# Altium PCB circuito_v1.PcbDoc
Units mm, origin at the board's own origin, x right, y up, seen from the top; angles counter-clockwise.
Board outline 81.15 x 71.75 mm, 2 copper layers (Top Layer, Bottom Layer); 45 components, 30 nets, 109 pads, 27 vias.
Unrouted connection lines stored in the file: 31.
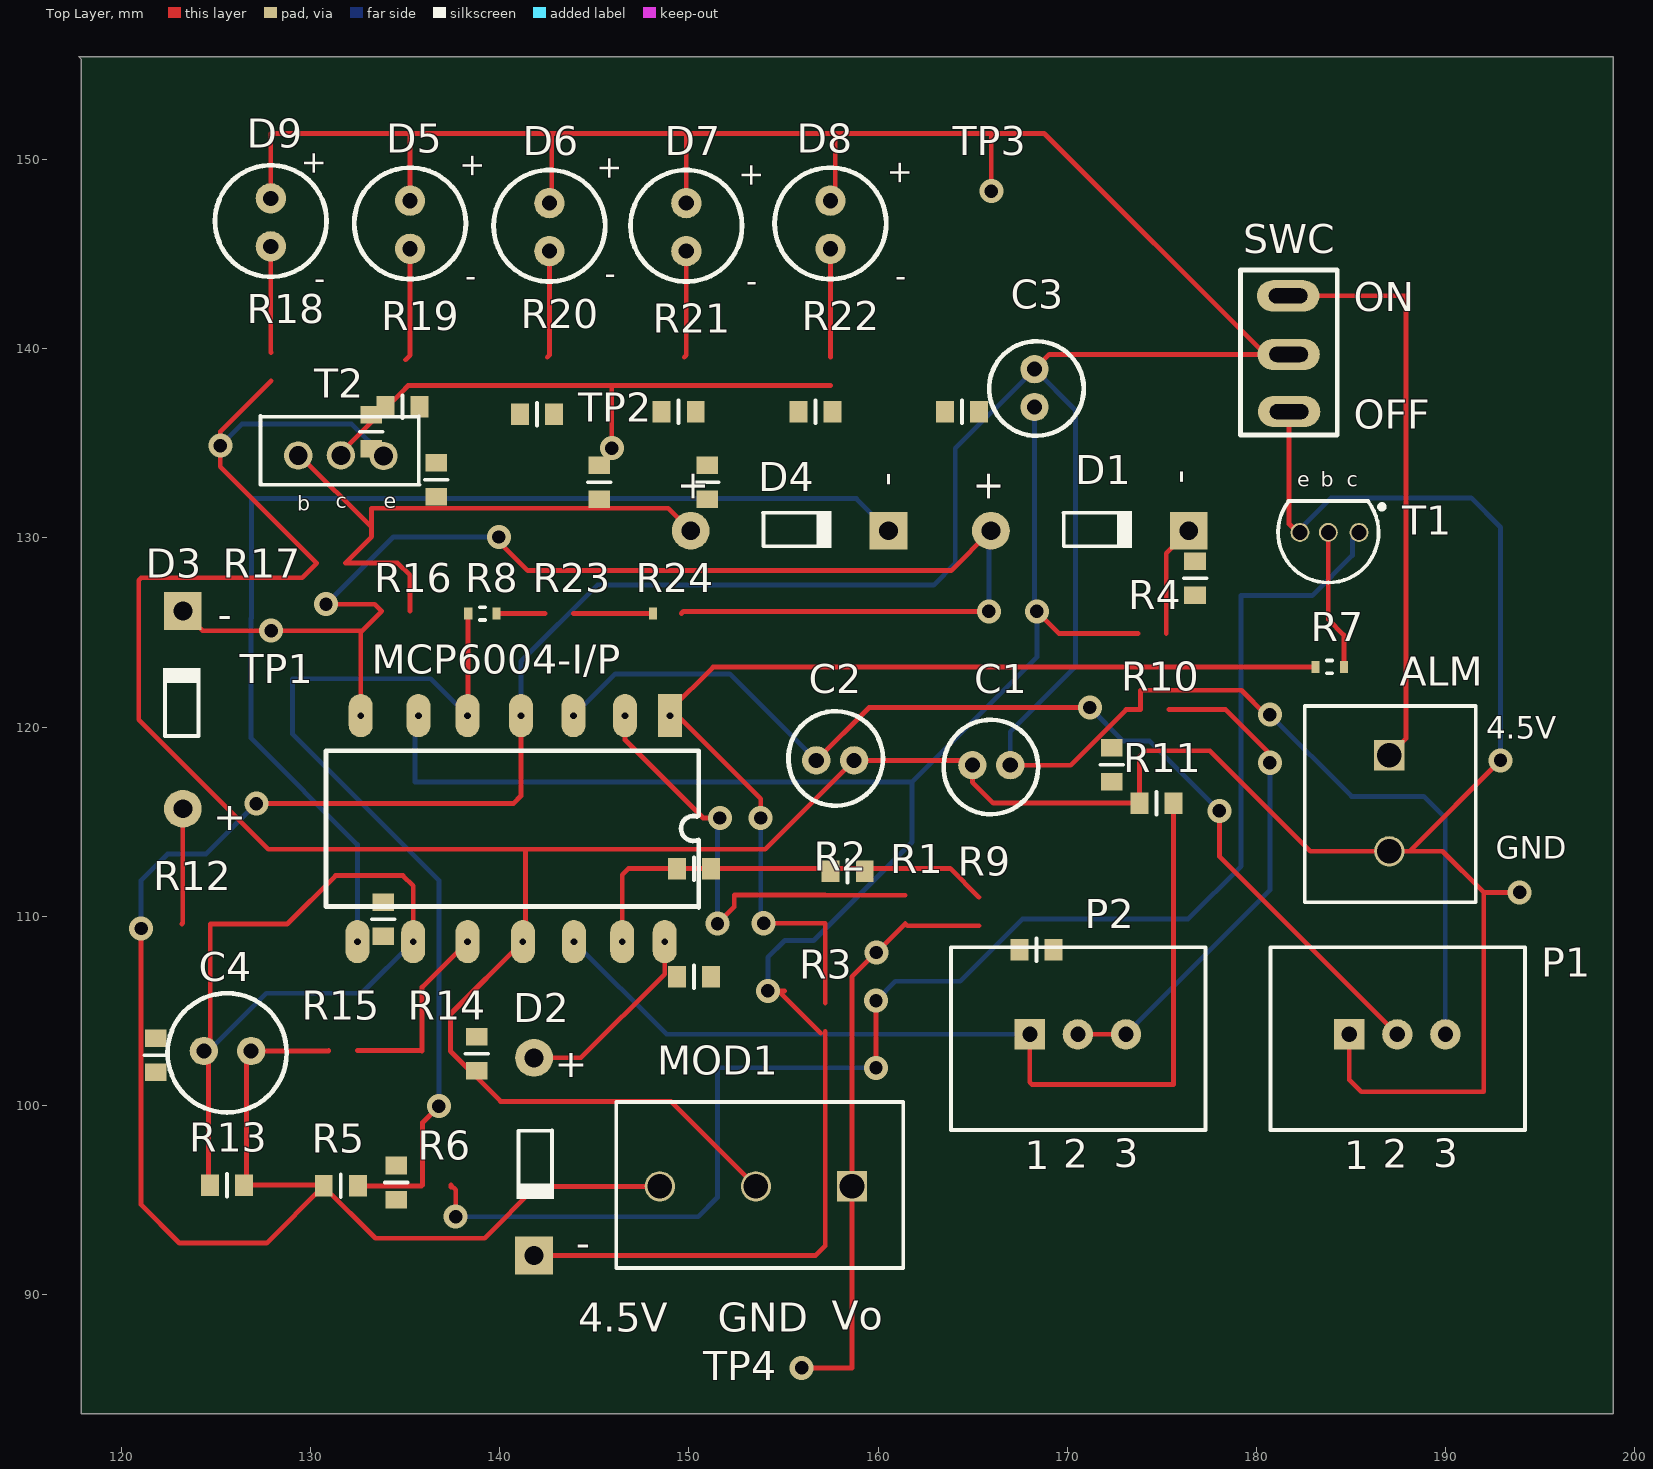
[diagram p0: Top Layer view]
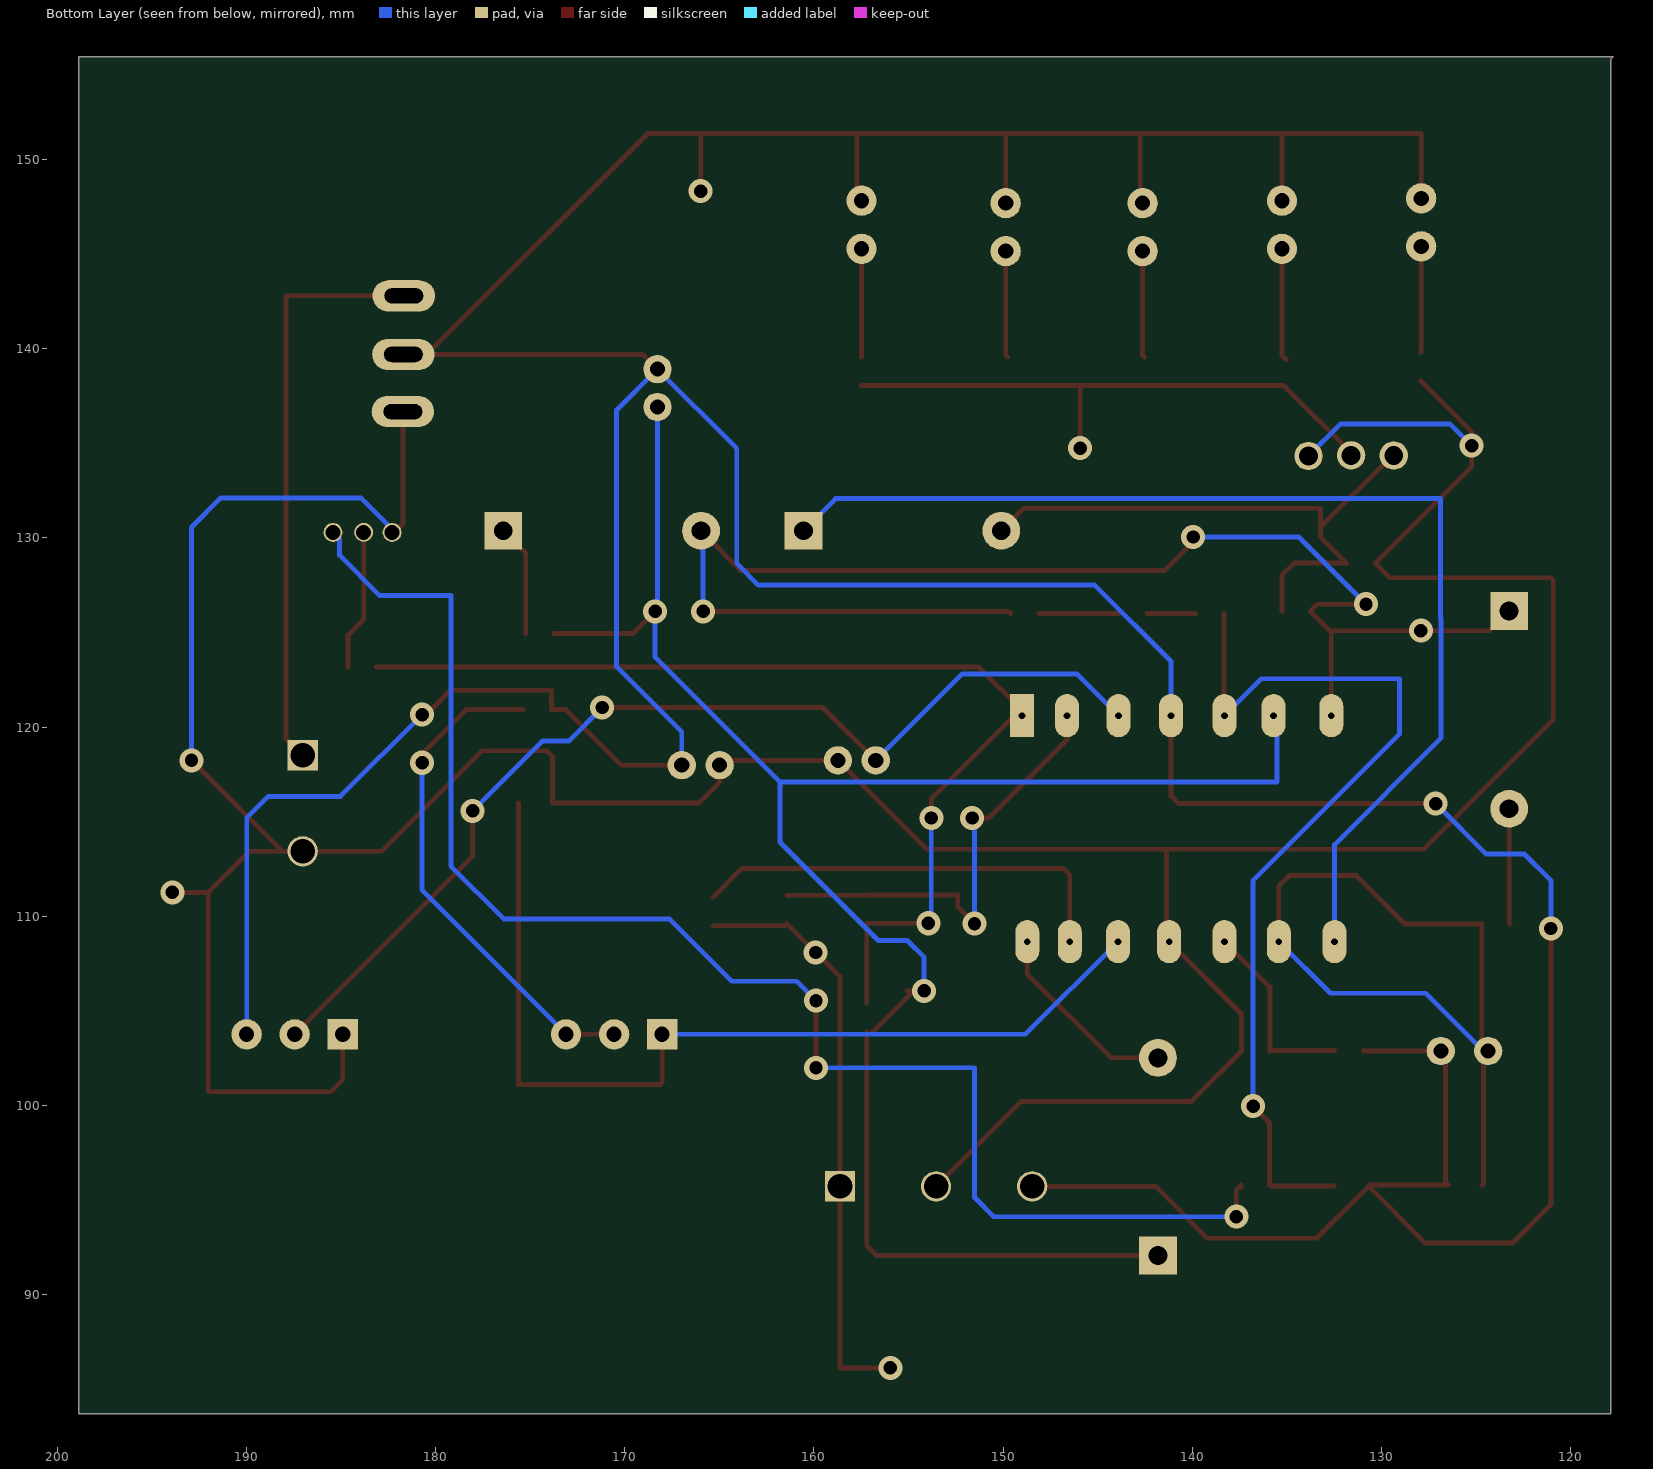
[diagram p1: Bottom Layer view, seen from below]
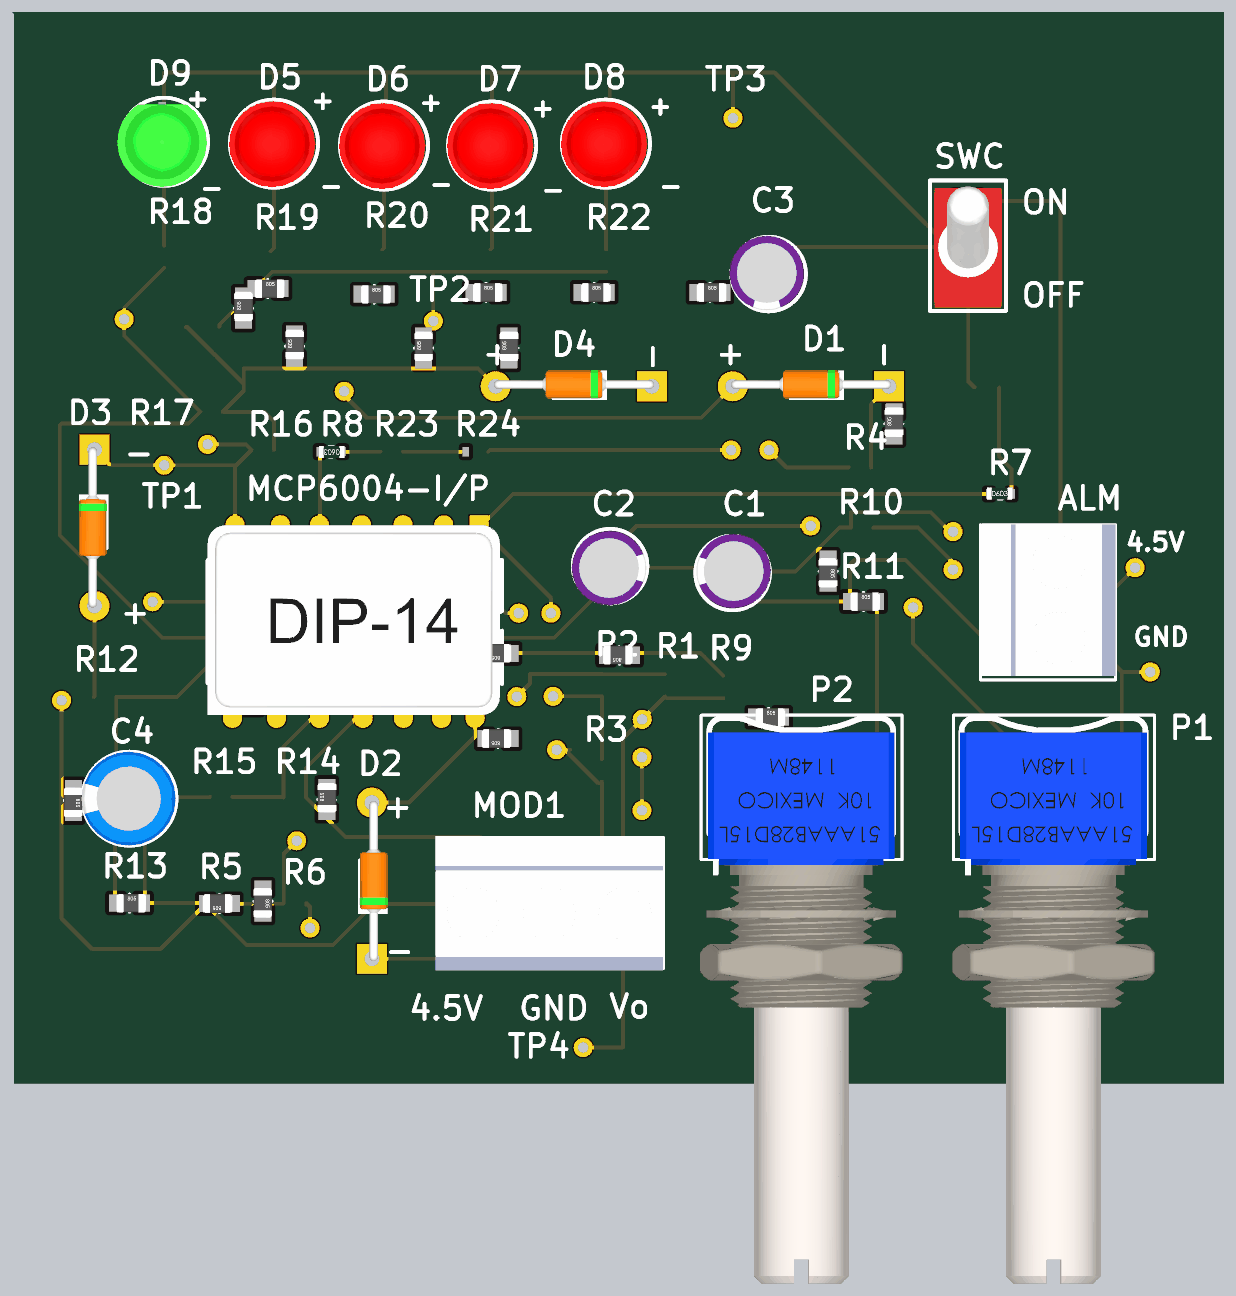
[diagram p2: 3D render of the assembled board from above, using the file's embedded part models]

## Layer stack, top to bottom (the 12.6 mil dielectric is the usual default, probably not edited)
Top Layer: signal copper 0.0356
Dielectric: dielectric 0.32, FR-4, Dk 4.8
Bottom Layer: signal copper 0.0356

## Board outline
117.729,155.448 198.882,155.448 198.882,83.693 117.856,83.693 117.856,155.321 117.729,155.448

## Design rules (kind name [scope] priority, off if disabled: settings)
Clearance Clearance_Vias_a_Mano [IsComponentBody vs IsVia] p1: gap=1.524
Clearance [All] p2: gap=0.254
MinimumSolderMaskSliver SilkscreenOverComponentPads [All] p2: minsoldermaskwidth=0.254
PolygonConnect [All] p1: connectstyle=Relief reliefconductorwidth=0.254 reliefentries=4 polygonreliefangle="90 Angle" airgapwidth=0.254
RoutingLayers RoutingLayers_1 [InNet('GND')] p1: top layer_v5=FALSE bottom layer_v5=FALSE
RoutingLayers [All] p2: top layer_v5=TRUE bottom layer_v5=TRUE
RoutingPriority RoutingPriority_GND [InNet('GND')] p1: routingpriority=0
RoutingPriority [All] p2: routingpriority=100
RoutingVias RoutingVias_A_Mano [All] p1: holewidth=0.889 width=2.032 viastyle="Through Hole" minholewidth=0.889 minwidth=1.778 maxholewidth=0.889 maxwidth=2.54
SolderMaskExpansion [All] p1: expansion=0.102
Width Width_Vcc [(InNet('VCC+') AND InNet('VCC-'))] p1: maxlimit=5.08 minlimit=1.778 preferedwidth=2.032
Width [All] p2: maxlimit=2.54 minlimit=0.254 preferedwidth=0.508
26 further rules are at their usual default settings.

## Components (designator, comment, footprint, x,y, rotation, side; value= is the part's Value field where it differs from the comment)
ALM "Header 2" ALM 170.434,105.029 r270 top
C1 "Cap" "Condensador 5mm" 165.989,117.983 r0 top
C2 "Cap" "Condensador 5mm" 157.734,118.237 r180 top
C3 "Cap" "Condensador 5mm" 168.275,137.922 r90 top
C4 "Cap" "Condensador 6.3mm" 125.603,102.87 r0 top
D1 "BAT85" BAT85 171.323,130.429 r270 top
D2 "Diode BAT18" BAT85 141.859,97.155 r180 top
D3 "Diode BAT18" BAT85 123.19,121.031 r0 top
D4 "Diode BAT18" BAT85 155.448,130.429 r270 top
D5 "LED" LED 135.255,147.828 r270 top
D6 "LED" LED 142.621,147.701 r270 top
D7 "LED" LED 149.86,147.701 r270 top
D8 "LED" LED 157.48,147.828 r270 top
D9 "LED" "LED verde" 127.889,147.955 r270 top
MCP6004-I/P "SW DIP-7" MCP6004 147.32,120.777 r270 top
MOD1 "Conector" Conector 122.428,104.521 r90 top
P1 "Res Tap" POTENCIOMETRO 187.452,103.759 r270 top
P2 "Res Tap" POTENCIOMETRO 170.561,103.759 r270 top
R1 "Res1" "SMD 0603"#1 161.417,110.363 r0 top
R2 "Res1" "SMD 0603"#1 157.226,110.363 r180 top
R3 "Res1" "SMD 0603"#1 157.226,104.648 r180 top
R4 "Res1" "SMD 0603"#1 174.498,124.968 r270 top
R5 "Res1" "SMD 0805" 138.557,93.599 r180 top
R6 "Res1" "SMD 0603"#1 136.652,95.758 r90 top
R7 "Res1" "SMD 0603"#2 183.896,123.19 r270 top
R8 "Res1" "SMD 0603"#2 139.065,125.984 r90 top
R9 "Res1" "SMD 0603"#1 165.354,110.236 r180 top
R10 "Res1" "SMD 0603"#1 174.625,120.904 r90 top
R11 "Res1" "SMD 0805" 167.767,118.11 r0 top
R12 "Res1" "SMD 0603"#1 123.952,109.601 r270 top
R13 "Res1" "SMD 0805" 118.618,97.917 r0 top
R14 "Res1" "SMD 0603"#1 136.652,102.87 r270 top
R15 "Res1" "SMD 0603"#1 131.699,102.87 r90 top
R16 "Res1" "SMD 0603"#1 134.493,126.111 r90 top
R17 "Res1" "SMD 0603"#1 131.064,128.651 r90 top
R18 "Res3" "SMD 0603"#1 127.889,139.065 r0 top
R19 "Res3" "SMD 0603"#1 135.001,138.684 r0 top
R20 "Res3" "SMD 0603"#1 142.494,138.811 r0 top
R21 "Res3" "SMD 0603"#1 149.733,138.811 r0 top
R22 "Res3" "SMD 0603"#1 157.48,138.811 r0 top
R23 "Res1" "SMD 0603"#1 143.129,125.984 r90 top
R24 "Res1" "SMD 0603"#3 148.844,125.984 r90 top
SWC "Conmutador" switch 182.372,138.684 r90 top
T1 "2N3904" "T1 BC550C" 173.482,189.865 r90 top
T2 "QNPN" "T2 BD139" 140.843,198.755 r90 top

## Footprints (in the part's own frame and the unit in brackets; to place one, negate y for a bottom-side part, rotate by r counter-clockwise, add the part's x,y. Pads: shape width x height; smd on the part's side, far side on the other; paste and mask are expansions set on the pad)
ALM [mm]
  rect 1.6x1.6 hole 1.3: 1(-13.48,16.6)
  round 1.6 hole 1.3: 2(-8.4,16.6)
  silkscreen extent -16.07,12.12 -5.7,21.17, body extent -16.1,12.18 -4.94,21.17, height 15.2
BAT85 [mm]
  round 2 hole 1: 1(0.049,-5.353)
  rect 2x2 hole 1: 2(0.049,5.107)
  silkscreen extent -1,-1.53 0.97,2.1, body extent -1.02,-5.46 0.88,5.26, height 1.95
"Condensador 5mm" [mm]
  round 1.5 hole 0.8: 1(-1,0) 2(1,0)
  silkscreen extent -2.52,-2.6 2.47,2.4, body extent -2.45,-2.47 2.55,2.52, height 11
"Condensador 6.3mm" [mm]
  round 1.5 hole 0.8: 1(-1.25,0) 2(1.25,0)
  silkscreen extent -3.17,-3.25 3.12,3.05, body extent -3.22,-3.25 3.08,3.05, height 11.5
Conector [mm]
  rect 1.6x1.6 hole 1.3: 1(-8.811,-36.193)
  round 1.6 hole 1.3: 2(-8.811,-31.113) 3(-8.811,-26.033)
  silkscreen extent -13.13,-38.9 -4.35,-23.72, body extent -13.25,-38.87 -4.25,-23.63, height 15.2
LED [mm]
  round 1.6 hole 0.8: 1(0,0) 2(2.54,0)
  silkscreen extent -1.75,-2.95 4.15,2.95, body extent -1.68,-3.03 4.12,2.77, height 17.5
"LED verde" [mm]
  round 1.6 hole 0.8: 1(0,0) 2(2.54,0)
  silkscreen extent -1.75,-2.95 4.15,2.95, body extent -1.47,-3.12 4.23,2.87, height 20.86
MCP6004 [mm]
  rect 2.286x1.27 hole 0.356: 1(0.175,1.675)
  oval 2.286x1.27 hole 0.356: 2(0.175,-0.7) 3(0.175,-3.425) 4(0.175,-6.2) 5(0.175,-9.025) 6(0.175,-11.625) 7(0.175,-14.675) 8(12.125,-14.85) 9(12.125,-11.9) 10(12.125,-9.025) 11(12.125,-6.1) 12(12.125,-3.4) 13(12.125,-0.85) 14(12.125,1.4)
  silkscreen extent 2.03,-16.51 10.33,3.2, body extent -0.3,-16.51 12.4,3.06, height 4.61
POTENCIOMETRO [mm]
  rect 1.6x1.6 hole 0.8: 1(0.008,-2.535)
  round 1.6 hole 0.8: 2(0.008,0.005) 3(0.008,2.545)
  silkscreen extent -4.6,-6.7 5.07,6.75, body extent -4.59,-6.77 33.45,6.77, height 14.1
"SMD 0603"#1 [mm]
  rect 0.94x1.14 smd mask+0.26: 1(6.062,-2.136) 2(7.862,-2.136)
  silkscreen extent 6.96,-2.74 6.96,-1.54, body extent 6.08,-2.77 8.08,-1.52, height 0.78
"SMD 0603"#2 [mm]
  rect 0.64x0.44 smd mask+0.26: 1(0.018,-0.76) 2(0.018,0.74)
  silkscreen extent -0.33,-0.15 0.35,0.13, body extent -0.4,-0.9 0.4,0.8, height 0.56
"SMD 0603"#3 [mm]
  rect 0.94x1.14 smd mask+0.26: 1(6.062,-2.136) 2(7.862,-2.136)
  rect 0.64x0.44 smd mask+0.26: 2(0.018,0.74)
  silkscreen extent 6.96,-2.74 6.96,-1.54, body extent 6.08,-2.77 8.08,-1.52, height 0.78
"SMD 0805" [mm]
  rect 0.94x1.14 smd mask+0.26: 1(6.062,-2.136) 2(7.862,-2.136)
  silkscreen extent 6.96,-2.74 6.96,-1.54, body extent 6.08,-2.77 8.08,-1.52, height 0.78
switch [mil]
  oval 65x130 hole 31.5 slot 80.71 at 90 deg: 1(-79,25) 2(40,26) 3(162,27)
  silkscreen extent -128,-75 216,126, body extent -119,-63 200,114, height 948
"T1 BC550C" [mm]
  round 1 hole 0.8: 1(-59.575,-11.95) 2(-59.571,-10.328) 3(-59.575,-8.825)
  silkscreen extent -62.23,-13.28 -57.92,-7.67, body extent -61.73,-12.63 -58.1,-7.87, height 4.92
"T2 BD139" [mm]
  round 1.5 hole 1: 1(-64.425,6.992) 2(-64.389,9.246) 3(-64.4,11.5)
  silkscreen extent -65.95,5.07 -62.3,13.5, body extent -65.4,5.4 -62.7,13.2, height 13.6

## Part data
ALM: "Header, 2-Pin"
C1 C2 C3 C4: "Capacitor"
D1: library part "Diode BAT18", "Low-Loss RF Switching Diode"
D2 D3 D4: "Low-Loss RF Switching Diode"
D5 D6 D7 D8 D9: library part LED2, "Typical RED, GREEN, YELLOW, AMBER GaAs LED"
MCP6004-I/P: "DIP Switch, 7 Position, SPST"
MOD1: library part "Header 3", "Header, 3-Pin"
P1 P2: "Tapped Resistor"
R1 R2 R3 R4 R5 R6 R7 R8 R9 R10 R11 R12 R13 R14 R15 R16 R17 R18 R19 R20 R21 R22 R23 R24: "Resistor"
T1: "NPN General Purpose Amplifier"
T2: "NPN Bipolar Transistor"

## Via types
v1: diameter 1.27, hole 0.711, Top Layer to Bottom Layer, 27 vias

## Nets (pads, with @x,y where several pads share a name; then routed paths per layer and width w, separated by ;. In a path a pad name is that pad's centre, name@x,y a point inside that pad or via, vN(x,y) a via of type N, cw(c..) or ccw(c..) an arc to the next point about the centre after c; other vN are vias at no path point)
GND: ALM.2 C1.1 C2.1 MCP6004-I/P.11 MOD1.2 P1.1 R11.1 R17.2 R18.1 SWC.1 T1.3 T2.1 | length 214.4
  Top Layer w0.254: 127.907,138.305 125.222,135.62 v1(125.222,134.874) 125.222,133.771 130.324,128.669 129.544,127.889 121.031,127.889 120.904,127.762 120.904,120.396 127.762,113.538 141.351,113.538 ; MOD1.2 149.048,100.203 140.041,100.203 137.392,102.852 137.392,104.824 MCP6004-I/P.11 141.351,108.783 141.351,113.538 ; SWC.1 181.737,130.735 T1.3@182.157,130.315 ; P1.1 184.917,101.341 185.547,100.711 192.024,100.711 192.024,111.252 ; v1(192.913,118.237) 188.105,113.429 ; v1(193.929,111.252) 192.024,111.252 ; 141.351,113.538 154.035,113.538 C2.1 164.735,118.237 C1.1 164.989,117.078 166.093,115.974 R11.1 173.829,118.457 174.117,118.745 177.546,118.745 182.862,113.429 ALM.2 188.105,113.429 ; 188.105,113.429 189.847,113.429 192.024,111.252
  Bottom Layer w0.254: v1(125.222,134.874) 126.365,136.017 132.164,136.017 T2.1 ; T1.3@182.157,130.315 183.953,132.111 191.358,132.111 192.913,130.556 v1(192.913,118.237)
NetALM_1: ALM.1 SWC.3 | length 30.9
  Top Layer w0.254: SWC.3 187.909,142.799 187.909,119.384 ALM.1
NetD1_3: D1.2 R4.2 | length 5.9
  Top Layer w0.254: 175.238,124.95 175.238,129.188 D1.2
NetD2_1: D2.1 MCP6004-I/P.14 | length 10.5
  Top Layer w0.254: D2.1 144.291,102.508 148.72,106.937 MCP6004-I/P.14
NetD3_1: D3.1 R12.1 | length 6.1
  Top Layer w0.254: 123.192,109.583 123.239,109.63 D3.1
NetD4_1: D4.1 R16.1 R17.1 T2.3 | length 31.9
  Top Layer w0.254: T2.3 129.424,134.355 133.223,130.556 ; 135.253,126.129 135.253,128.018 134.602,128.669 131.824,128.669 133.223,130.068 133.223,131.572 148.903,131.572 D4.1
NetD5_2: D5.2 R19.2 | length 6
  Top Layer w0.254: 135.019,139.424 135.255,139.66 D5.2
NetD6_2: D6.2 R20.2 | length 5.7
  Top Layer w0.254: 142.512,139.551 142.621,139.66 D6.2
NetD7_2: D7.2 R21.2 | length 5.7
  Top Layer w0.254: 149.751,139.551 149.86,139.66 D7.2
NetD8_2: D8.2 R22.2 | length 5.7
  Top Layer w0.254: D8.2 157.48,139.569 157.498,139.551
NetD9_2: D9.2 R18.2 | length 5.6
  Top Layer w0.254: D9.2 127.889,139.823 127.907,139.805
NetMOD1_1: MOD1.1 R1.1 R9.2 | length 31.3
  Top Layer w0.254: v1(155.958,86.108) 158.621,86.108 MOD1.1 158.621,106.789 161.435,109.603 161.542,109.496 165.336,109.496
  other v1: 159.909,108.077
NetP2_1: P2.2 P2.3 R10.1 | length 26.8
  Top Layer w0.254: P2.2 P2.3 ; 175.385,120.922 178.377,120.922 180.721,118.578 v1(180.721,118.11)
  Bottom Layer w0.254: P2.3 180.721,111.366 v1(180.721,118.11)
NetR6_1: R6.1 T1.1 | length 79.3
  Top Layer w0.254: 137.412,95.673 137.412,95.776 137.668,95.52 v1(137.668,94.107) ; v1(159.893,101.981) v1(159.893,105.537)
  Bottom Layer w0.254: v1(137.668,94.107) 150.495,94.107 151.511,95.123 151.511,101.981 v1@159.512,101.981 ; v1(159.893,105.537) 160.909,106.553 164.338,106.553 167.64,109.855 176.403,109.855 179.197,112.649 179.197,126.951 182.958,126.951 185.08,129.073 185.08,129.938 T1.1@185.457,130.315
NetR7_2: R7.2 T1.2 | length 7.5
  Top Layer w0.254: T1.2 183.81,125.689 184.636,124.863 R7.2
NetR8_1: R8.1 R23.2 | length 2.6
  Top Layer w0.254: R8.1 142.389,126.002
NetR19_1: R19.1 R20.1 R21.1 R22.1 T2.2 | length 31.2
  Top Layer w0.254: T2.2 131.597,134.502 135.019,137.924 135.146,138.051 142.512,138.051 145.923,138.051 ; v1@145.923,134.366 145.923,138.051 ; 157.498,138.051 149.751,138.051 145.923,138.051
  other v1: 145.923,134.747
NetR23_1: R24.2@148.104,126.002 | length 4.2
  Top Layer w0.254: 143.889,126.002 R24.2@148.104,126.002
VA+: C2.2 MCP6004-I/P.3 P1.2 | length 56.4
  Top Layer w0.254: C2.2 159.528,121.031 v1(171.196,121.031) ; v1@178.054,115.824 178.051,115.821 v1(178.051,115.57) 178.051,113.157 P1.2
  Bottom Layer w0.254: MCP6004-I/P.3 146.102,122.809 152.162,122.809 C2.2 ; v1(171.196,121.031) 172.974,119.253 174.368,119.253 v1(178.051,115.57)
VA-: MCP6004-I/P.2 R1.2 R2.1 | length 24.8
  Top Layer w0.254: MCP6004-I/P.2 146.62,119.318 150.749,115.189 v1(151.638,115.189) ; v1(151.511,109.601) 152.398,110.488 152.398,111.123 157.208,111.123 157.228,111.103 161.435,111.103
  Bottom Layer w0.254: v1@151.638,109.728 v1(151.511,109.601) 151.511,115.062 v1(151.638,115.189)
VB+: MCP6004-I/P.5 R5.1 R6.2 R8.2 | length 49.3
  Top Layer w0.254: R5.1 135.871,95.735 135.912,95.776 135.912,99.082 v1(136.779,99.949) ; MCP6004-I/P.5 138.325,120.632 R8.2
  Bottom Layer w0.254: v1(136.779,99.949) 136.779,111.887 129.032,119.634 129.032,122.555 136.342,122.555 MCP6004-I/P.5
VB-: C3.1 D2.2 MCP6004-I/P.6 R3.2 R4.1 | length 104.3
  Top Layer w0.254: D2.2 156.691,92.048 157.208,92.565 157.208,103.908 ; v1(154.178,106.045) 155.071,106.045 ; 154.835,105.945 156.972,103.808 ; v1(168.402,126.111) 169.563,124.95 173.738,124.95
  Bottom Layer w0.254: MCP6004-I/P.6 135.509,120.416 135.509,117.094 161.798,117.094 ; v1(154.178,106.045) 154.178,107.823 155.067,108.712 156.591,108.712 161.798,113.919 161.798,117.094 ; C3.1 168.275,126.238 v1(168.402,126.111) 168.402,123.698 161.798,117.094
VC+: MCP6004-I/P.10 R14.1 R15.1 | length 10.2
  Top Layer w0.254: 132.459,102.888 135.856,102.888 135.892,102.852 135.892,106.249 MCP6004-I/P.10
VC-: C4.1 MCP6004-I/P.9 R12.2 R13.1 | length 42
  Top Layer w0.254: R13.1 124.603,95.858 124.603,102.87 124.692,102.959 124.692,109.583 128.76,109.583 131.318,112.141 134.874,112.141 135.42,111.595 MCP6004-I/P.9
  Bottom Layer w0.254: C4.1@124.603,102.87 127.651,105.918 132.686,105.918 MCP6004-I/P.9
"VCC (4.5 V)": C1.2 C3.2 C4.2 D5.1 D6.1 D7.1 D8.1 D9.1 MCP6004-I/P.4 MOD1.3 P1.3 R5.2 R10.2 R13.2 SWC.2 | length 286.1
  Top Layer w0.254: v1@121.285,109.601 v1(121.031,109.347) 121.031,94.742 123.063,92.71 127.67,92.71 R5.2 ; v1(127.127,115.951) 140.716,115.951 141.12,116.355 MCP6004-I/P.4 ; D9.1 127.889,151.384 135.255,151.384 ; 130.959,102.888 130.941,102.87 126.603,102.87 126.603,95.904 R13.2 130.649,95.781 R5.2 ; D5.1 135.255,151.384 ; D6.1 142.748,147.828 142.748,151.384 ; MOD1.3 141.938,95.71 139.192,92.964 133.427,92.964 130.695,95.696 R5.2 ; D7.1 149.86,151.384 ; D8.1 157.734,148.082 157.734,151.384 ; v1(165.989,148.336) 165.989,151.384 ; C1.2 170.18,117.983 173.119,120.922 173.885,120.922 173.885,121.942 179.219,121.942 180.511,120.65 v1(180.721,120.65) ; C3.2 169.053,139.7 SWC.2@180.467,139.7 ; SWC.2 SWC.2@180.467,139.7 ; 135.255,151.384 142.748,151.384 ; 142.748,151.384 149.86,151.384 ; 149.86,151.384 157.734,151.384 ; 157.734,151.384 165.989,151.384 ; 165.989,151.384 168.783,151.384 SWC.2@180.467,139.7
  Bottom Layer w0.254: v1(121.031,109.347) 121.031,111.887 122.428,113.284 124.46,113.284 v1@127,115.824 ; MCP6004-I/P.4 141.12,123.467 145.161,127.508 162.941,127.508 164.084,128.651 164.084,134.731 C3.2 170.434,136.763 170.434,123.19 166.989,119.745 C1.2 ; v1(180.721,120.65) 185.039,116.332 188.859,116.332 189.997,115.194 P1.3
VD+: MCP6004-I/P.12 P2.1 R11.2 | length 51.2
  Top Layer w0.254: P2.1 168.026,101.214 168.136,101.104 175.629,101.104 R11.2
  Bottom Layer w0.254: MCP6004-I/P.12 148.821,103.751 P2.1
VD-: MCP6004-I/P.13 R9.1 | length 23.2
  Top Layer w0.254: MCP6004-I/P.13 146.47,112.18 146.812,112.522 163.81,112.522 165.336,110.996
VOUTA: MCP6004-I/P.1 R2.2 R3.1 R7.1 | length 55.5
  Top Layer w0.254: v1(153.797,115.189) 153.797,116.205 149.4,120.602 MCP6004-I/P.1 148.995,120.892 151.275,123.172 R7.1 R7.1@183.118,123.19 ; v1(153.946,109.623) 157.208,109.623 157.208,105.408
  Bottom Layer w0.254: v1@153.797,110.236 v1(153.797,115.189)
VOUTB: D1.1 D3.2 MCP6004-I/P.7 R16.2 | length 77.7
  Top Layer w0.254: D3.2 124.286,125.091 132.715,125.091 ; v1(130.81,126.492) 133.39,126.492 133.753,126.129 132.715,125.091 ; MCP6004-I/P.7 132.645,125.021 132.715,125.091 ; v1@139.954,129.794 141.478,128.27 163.86,128.27 D1.1 ; 149.604,126.002 149.713,126.111 v1(165.862,126.111)
  Bottom Layer w0.254: v1(130.81,126.492) 134.366,130.048 v1(139.954,130.048) ; v1(165.862,126.111) 165.862,130.272 D1.1
  other v1: 127.907,125.095
VOUTC: D4.2 MCP6004-I/P.8 | length 60.2
  Bottom Layer w0.254: MCP6004-I/P.8 132.47,113.783 126.846,119.407 126.846,125.73 126.873,125.757 126.873,132.08 158.855,132.08 D4.2
pads on no net: R14.2 R15.2 R23.1 R24.1 R24.2@150.98,133.846

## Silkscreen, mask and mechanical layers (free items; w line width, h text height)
Top Overlay:
  text "TP3" at 163.957,150.241 h1.52
  text "TP2" at 144.145,136.144 h1.52
  text "TP1" at 126.238,122.301 h1.52
  text "TP4" at 150.749,85.471 h1.52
